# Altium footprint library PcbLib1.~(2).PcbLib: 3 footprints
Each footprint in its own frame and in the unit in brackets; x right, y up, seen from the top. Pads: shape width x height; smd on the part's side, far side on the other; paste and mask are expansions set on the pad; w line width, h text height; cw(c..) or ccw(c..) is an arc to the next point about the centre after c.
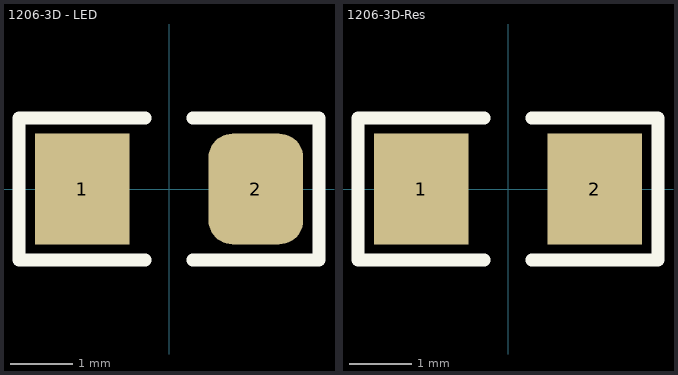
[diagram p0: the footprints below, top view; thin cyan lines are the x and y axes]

## 1206-3D - LED [mil]
pads (2):
  rect 60x70 smd: 1(-55,0)
  rrect50% 60x70 smd: 2(55,0)
Top Overlay:
  lines w8: -15,-45 -95,-45 -95,45 -15,45 ; 15,-45 95,-45 95,45 15,45
3D body "User Library-LED 1206 RED.STEP": height 43.31, standoff 0, extent -61.99,-31.49 63.99,31.5

## 1206-3D-Res [mil]
pads (2):
  rect 60x70 smd: 1(-55,0) 2(55,0)
Top Overlay:
  lines w8: -15,-45 -95,-45 -95,45 -15,45 ; 15,-45 95,-45 95,45 15,45
3D body "SW3dPS-1206 SMD Resistor.STEP": height 39.45, standoff 0, extent -62.99,-31.5 62.99,31.5

## PCBComponent_1 [mil]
